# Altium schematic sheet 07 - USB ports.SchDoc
size B; CompanyName: Microchip Technology Inc.; Organization: Microchip Technology; Address1: 2355 West Chandler Blvd.; Address2: Chandler, AZ  85224; Address4: USA; DocumentNumber: 7; SheetNumber: 7; SheetTotal: 13; SheetTitle: USB interfaces
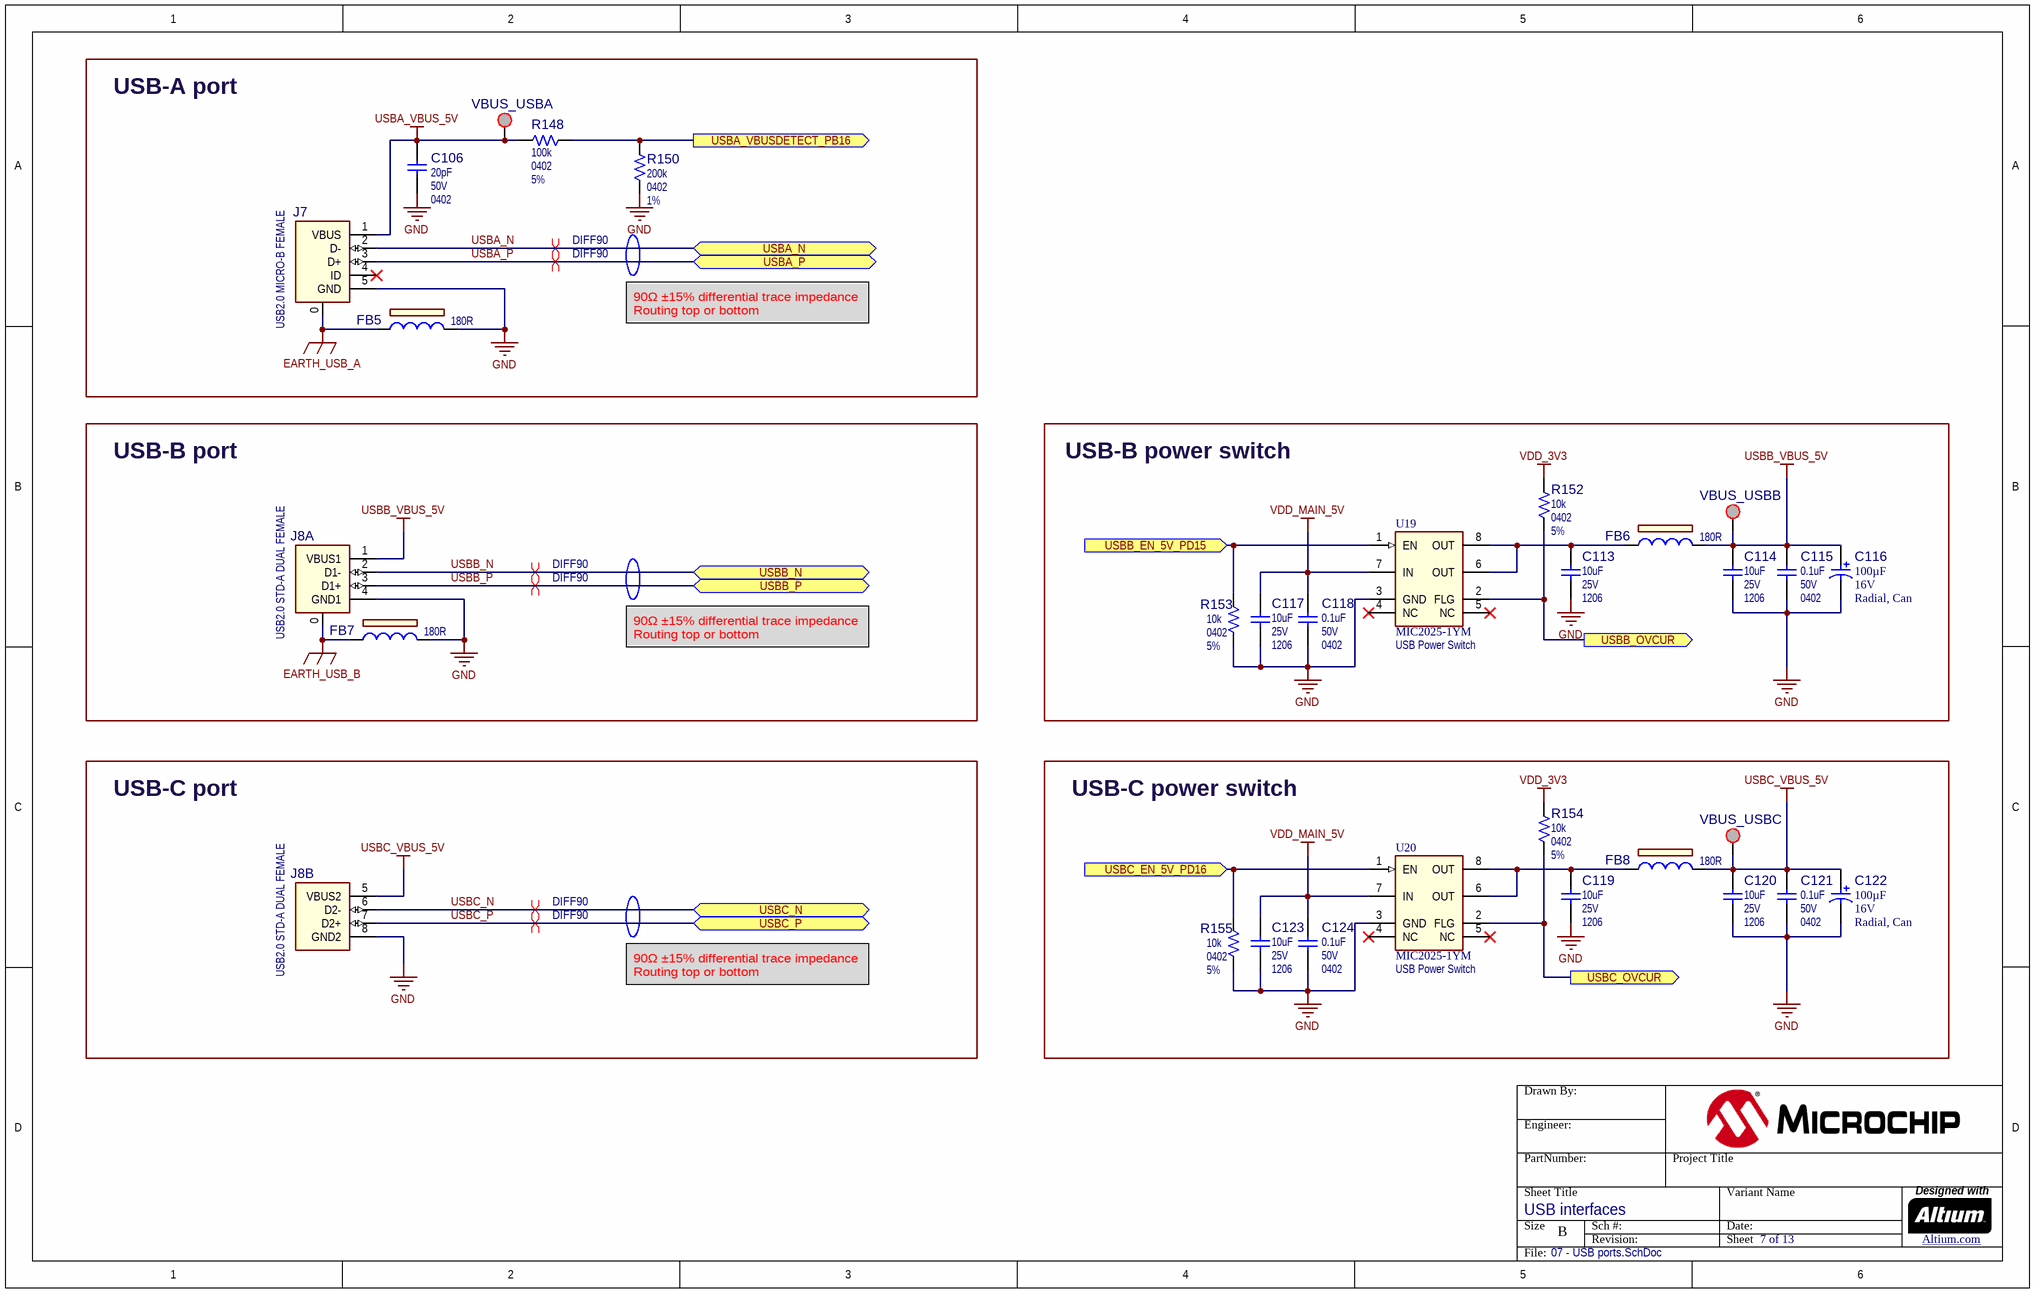
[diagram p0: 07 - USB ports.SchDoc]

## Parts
?  (no value)  (graphical)
C106  value 20pF  Voltage: 50V  Package: 0402  [CAP_C_0402]  (hidden comment: Capacitor NP)
C113  value 10uF  Voltage: 25V  Package: 1206  [CAP_C_1206]  (hidden comment: Capacitor NP)
C114  value 10uF  Voltage: 25V  Package: 1206  [CAP_C_1206]  (hidden comment: Capacitor NP)
C115  value 0.1uF  Voltage: 50V  Package: 0402  [CAP_C_0402]  (hidden comment: Capacitor NP)
C116  value 100µF  Voltage: 16V  Package: Radial, Can  [CAP_RAD_P2D5H12.5]  (hidden comment: Capacitor POL)
C117  value 10uF  Voltage: 25V  Package: 1206  [CAP_C_1206]  (hidden comment: Capacitor NP)
C118  value 0.1uF  Voltage: 50V  Package: 0402  [CAP_C_0402]  (hidden comment: Capacitor NP)
C119  value 10uF  Voltage: 25V  Package: 1206  [CAP_C_1206]  (hidden comment: Capacitor NP)
C120  value 10uF  Voltage: 25V  Package: 1206  [CAP_C_1206]  (hidden comment: Capacitor NP)
C121  value 0.1uF  Voltage: 50V  Package: 0402  [CAP_C_0402]  (hidden comment: Capacitor NP)
C122  value 100µF  Voltage: 16V  Package: Radial, Can  [CAP_RAD_P2D5H12.5]  (hidden comment: Capacitor POL)
C123  value 10uF  Voltage: 25V  Package: 1206  [CAP_C_1206]  (hidden comment: Capacitor NP)
C124  value 0.1uF  Voltage: 50V  Package: 0402  [CAP_C_0402]  (hidden comment: Capacitor NP)
FB5  value 180R  [IND_C_0603]  (hidden comment: Ferrite Bead)
FB6  value 180R  [IND_C_0603]  (hidden comment: Ferrite Bead)
FB7  value 180R  [IND_C_0603]  (hidden comment: Ferrite Bead)
FB8  value 180R  [IND_C_0603]  (hidden comment: Ferrite Bead)
J7  value USB2.0 MICRO-B FEMALE  [CON_USB_Micro-AB_SMD_TH_RA_FCI_10118194-0001LF]  (hidden comment: CON USB2.0 Mini_Micro)
J8  value USB2.0 STD-A DUAL FEMALE  [CON_USB2.0-A_Dual_RCPT_TH_RA_AMN_AU-Y1008-2]  (hidden comment: CON USB2.0 A DUAL)  (parts A,B of 2)
R148  value 100k  Package: 0402  Tolerance: 5%  [RES_C_0402]  (hidden comment: Resistor)
R150  value 200k  Package: 0402  Tolerance: 1%  [RES_C_0402]  (hidden comment: Resistor)
R152  value 10k  Package: 0402  Tolerance: 5%  [RES_C_0402]  (hidden comment: Resistor)
R153  value 10k  Package: 0402  Tolerance: 5%  [RES_C_0402]  (hidden comment: Resistor)
R154  value 10k  Package: 0402  Tolerance: 5%  [RES_C_0402]  (hidden comment: Resistor)
R155  value 10k  Package: 0402  Tolerance: 5%  [RES_C_0402]  (hidden comment: Resistor)
U19  MIC2025-1YM  value USB Power Switch  [SOIC-8]
U20  MIC2025-1YM  value USB Power Switch  [SOIC-8]
VBUS_USBA  SMD Test Point  [TP_1x1_SMD]  (value not drawn)  (no BOM)
VBUS_USBB  SMD Test Point  [TP_1x1_SMD]  (value not drawn)  (no BOM)
VBUS_USBC  SMD Test Point  [TP_1x1_SMD]  (value not drawn)  (no BOM)

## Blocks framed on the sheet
USB-A port: C106 FB5 J7 R148 R150 VBUS_USBA
USB-B port: FB7 J8
USB-B power switch: C113-C118 FB6 R152 R153 U19 VBUS_USBB
USB-C port: J8
USB-C power switch: C119-C124 FB8 R154 R155 U20 VBUS_USBC

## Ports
USBA_N (bidir), USBA_P (bidir), USBA_VBUSDETECT_PB16 (out), USBB_EN_5V_PD15 (in), USBB_N (bidir), USBB_OVCUR (out), USBB_P (bidir), USBC_EN_5V_PD16 (in), USBC_N (bidir), USBC_OVCUR (out), USBC_P (bidir)

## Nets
EARTH_USB_A: FB5.1 J7.0(SHLD)
EARTH_USB_B: FB7.1 J8.0(SHLD)
GND: C106.1 C113.2 C114.2 C115.2 C116.2 C117.2 C118.2 C119.2 C120.2 C121.2 C122.2 C123.2 C124.2 FB5.2 FB7.2 J7.5(GND) J8.4(GND1) J8.8(GND2) R150.1 R153.1 R155.1 U19.3(GND) U20.3(GND)
USBA_VBUS_5V: C106.2 J7.1(VBUS) R148.1 VBUS_USBA.1
USBB_VBUS_5V: C114.1 C115.1 C116.1 FB6.2 J8.1(VBUS1) VBUS_USBB.1
USBC_VBUS_5V: C120.1 C121.1 C122.1 FB8.2 J8.5(VBUS2) VBUS_USBC.1
VDD_3V3: R152.2 R154.2
VDD_MAIN_5V: C117.1 C118.1 C123.1 C124.1 U19.7(IN) U20.7(IN)
USBA_N: J7.2(D-) ; port USBA_N
USBA_P: J7.3(D+) ; port USBA_P
USBA_VBUSDETECT_PB16: R148.2 R150.2 ; port USBA_VBUSDETECT_PB16
USBB_EN_5V_PD15: R153.2 U19.1(EN) ; port USBB_EN_5V_PD15
USBB_N: J8.2(D1-) ; port USBB_N
USBB_OVCUR: R152.1 U19.2(FLG) ; port USBB_OVCUR
USBB_P: J8.3(D1+) ; port USBB_P
USBC_EN_5V_PD16: R155.2 U20.1(EN) ; port USBC_EN_5V_PD16
USBC_N: J8.6(D2-) ; port USBC_N
USBC_OVCUR: R154.1 U20.2(FLG) ; port USBC_OVCUR
USBC_P: J8.7(D2+) ; port USBC_P
NetC113_1: C113.1 FB6.1 U19.6(OUT) U19.8(OUT)
NetC119_1: C119.1 FB8.1 U20.6(OUT) U20.8(OUT)

Not connected (* = marked no-connect by the designer): J7 4(ID)*; U19 4(NC)* 5(NC)*; U20 4(NC)* 5(NC)*

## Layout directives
differential pair; differential pair class DIFF90; net class DIFF90; rule Matched Net Lengths [Tolerance = 10mil]: USBA_N, USBA_P, USBB_N, USBB_P, USBC_N, USBC_P

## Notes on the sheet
- 90Ω ±15% differential trace impedance
  Routing top or bottom

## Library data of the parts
? = Title Block B
C106 = CAP0364: Capacitor; Manufacturer 1: Murata; Manufacturer Part Number 1: GRM1555C1H200JZ01D; Description_: CAP CER 20pF 50V 5% C0G SMD 0402; Dev Tools Status: Production; Tolerance: 5%; Temperature Coeffcient: C0G; Type: Ceramic; Populated: YES
C113 C114 C117 C119 C120 C123 = CAP1418: Capacitor; Manufacturer 1: Samsung Electro-Mechanics America, Inc; Manufacturer Part Number 1: CL31B106KAHNFNE; Description_: CAP CER 10uF 25V 10% X7R SMD 1206; Dev Tools Status: Design; Tolerance: 10%; Temperature Coeffcient: X7R; Type: Ceramic; Populated: YES; Owner: Sorin Stanoaia
C115 C118 C121 C124 = CAP1463: Capacitor; Manufacturer 1: TDK Corporation; Manufacturer Part Number 1: C1005X7R1H104K050BB; Description_: CAP CER 0.1uF 50V 10% X7R SMD 0402; Dev Tools Status: Production; Tolerance: 10%; Temperature Coeffcient: X7R; Type: Ceramic; Owner: Jamus Griego; Populated: YES
C116 C122 = CAP1834: Capacitor; Manufacturer 1: Wurth Electronics Inc.; Manufacturer Part Number 1: 860010372006; Description_: CAP 100 UF 20% 16 V; Dev Tools Status: Design; Tolerance: ±20%; Type: Aluminum; Owner: Ed Kennedy; Populated: YES
FB5-FB8 = IND1453: FERRITE 180R 1.5A SMD 0603; Manufacturer 1: Murata Electronics North America; Manufacturer Part Number 1: BLM18PG181SN1D; Dev Tools Status: Production; Owner: Dragos Danaila; DCR: 0.09R; Test Frequency: 100MHz; Populated: YES
J7 = CON1383: Connector USB Mini; Manufacturer 1: FCI; Manufacturer Part Number 1: 10118194-0001LF; Description_: CON USB2.0 MICRO-B FEMALE TH/SMD R/A; Dev Tools Status: Production; Owner: Jamus Griego; Populated: YES
J8 = CON1430: Connector USB DUAL; Manufacturer 1: Assmann WSW Components; Manufacturer Part Number 1: AU-Y1008-2; Description_: CON USB2.0 STD-A DUAL FEMALE TH R/A; Dev Tools Status: Design; Owner: Sorin Stanoaia; Current: 1.5A; Populated: YES
R148 = RES2196: Manufacturer 1: Yageo; Manufacturer Part Number 1: RC0402JR-07100KL; Description_: RES TKF 100k 5% 1/16W SMD 0402; Dev Tools Status: Design; Temperature Coeffcient: 100ppm/C; Power: 1/16W; Owner: Ilie Galan; Populated: YES
R150 = RES1424: Manufacturer 1: Panasonic; Manufacturer Part Number 1: ERJ-2RKF2003X; Description_: RES TKF 200k 1% 1/10W SMD 0402; Dev Tools Status: Production; Voltage: 50V; Temperature Coeffcient: 100ppm/C; Power: 1/10W; Owner: Tad Ahlvers; Populated: YES
R152-R155 = RSMT0439: Manufacturer 1: Vishay; Manufacturer Part Number 1: CRCW040210K0JNED; Description_: RES TKF 10k 5% 1/16W SMD 0402; Dev Tools Status: Production; Voltage: 50V; Temperature Coeffcient: 100ppm/C; Power: 1/16W; Populated: Yes
U19 U20 = MIC7234: Manufacturer 1: Microchip Technology; Dev Tools Status: Production; Owner: Dragos Danaila; Populated: YES
VBUS_USBA VBUS_USBB VBUS_USBC = TEST-POINT: Test Point pad 1.00mm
